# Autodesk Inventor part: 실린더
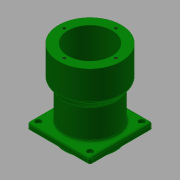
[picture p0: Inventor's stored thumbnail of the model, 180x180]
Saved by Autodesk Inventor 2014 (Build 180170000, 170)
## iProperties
Created: 2016-11
Part Number: 실린더
Material: 알루미늄 6061
Document SubType Name: Modeling
Designer: mduedu
Density: 2.71 g/cm^3
Appearance: 진녹색
Mass: 592.083 g
Surface Area: 591.531 cm^2
Volume: 218.481 cm^3
Author: mduedu
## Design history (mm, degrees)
sketch "스케치1"
  geometry: L1 (0, 0)-(0, 110); L2 (30, 0)-(30, 110); L3 (30, 110)-(42.5, 110); L4 (42.5, 110)-(42.5, 70); L5 (42.5, 70)-(35, 60); L6 (35, 60)-(35, 0); L7 (35, 0)-(30, 0)
  constraints: 14 end point, 4 parallel, 2 horizontal alignment, 1 perpendicular, 1 vertical
  dimensions: "d0" = 110 distance of L1.start L1.end; "d1" = 60 diameter of L2.end L1; "d2" = 85 diameter of L3.end L1; "d3" = 70 diameter of L6.end L1; "d4" = 40 distance of L3.end L4.end; "d5" = 50 vertical distance of L5.end L3.end
revolve "회전1" sketch "스케치1" stored, may be unused: angle "d6" = 90 deg
node "작업 평면1"
sketch "스케치2"
  geometry: L1 (-42.5, -42.5)-(42.5, -42.5); L2 (42.5, -42.5)-(42.5, 42.5); L3 (42.5, 42.5)-(-42.5, 42.5); L4 (-42.5, 42.5)-(-42.5, -42.5); L5 (-42.5, -42.5)-(42.5, 42.5); L6 (42.5, -42.5)-(-42.5, 42.5); C1 r 35 at (0, 0) reference; C2 r 35 at (0, 0); 1 further point
  constraints: 12 end point, 2 midpoint, 2 parallel, 2 perpendicular, 1 centre point, 1 coincident, 1 concentric, 1 horizontal
  dimensions: "d8" = 85 distance of L2.end L3.end
extrude "돌출1" join sketch "스케치2" distance "d10" = 8; taper "d11" = 0 deg
fillet "모깎기1" dims "d12" = 3
fillet "모깎기2" dims "d13" = 3
chamfer "모따기1" distance "d14" = 1; stored, may be unused: second distance "d15" = 2, angle "d16" = 45 deg
chamfer "모따기2" distance "d17" = 5; stored, may be unused: second distance "d18" = 2, angle "d19" = 15 deg
sketch "스케치3"
  geometry: L1 (-35, -35)-(35, -35); L2 (35, -35)-(35, 35); L3 (35, 35)-(-35, 35); L4 (-35, 35)-(-35, -35); L5 (-35, -35)-(35, 35); L6 (35, -35)-(-35, 35); 5 further points
  constraints: 12 end point, 4 coincident, 2 midpoint, 2 parallel, 1 horizontal, 1 perpendicular
  dimensions: "d20" = 70 distance of L3.end L2.end; "d21" = 70 distance of L2.end L1.end
sketch "스케치4"
  geometry: 4 further points
  constraints: 4 other
hole "구멍1" sketch "스케치4" at (-35, 35), (35, 35), (35, -35), (-35, -35) diameter "d22" = 4.5; stored, may be unused: countersink angle "d26" = 90 deg, drill point angle "d28" = 0 deg; dims "d23" = 6, "d24" = 8, "d25" = 4.6, "d27" = 8
sketch "스케치5"
  geometry: 4 further points
  constraints: 4 other
hole "구멍2" sketch "스케치5" at (0, -35), (35, 0), (-35, 0), (0, 35) diameter "d29" = 4.134; stored, may be unused: countersink angle "d33" = 90 deg, drill point angle "d35" = 120 deg; dims "d30" = 7.5, "d31" = 4, "d32" = 2, "d34" = 10
node "솔리드1"
